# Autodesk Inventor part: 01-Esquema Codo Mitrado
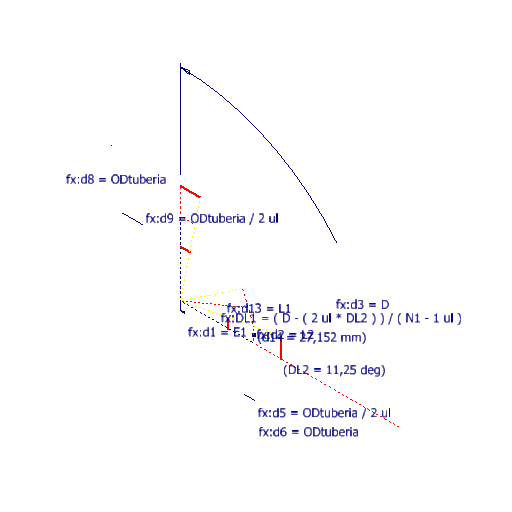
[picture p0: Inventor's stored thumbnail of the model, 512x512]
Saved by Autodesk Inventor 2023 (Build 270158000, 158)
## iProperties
Created: 2023-01
Part Number: 01-Esquema Codo Mitrado
Material: Generic
Document SubType Name: Modeling
Designer: Nelson C Agudelo A
Density: 1 g/cm^3
Appearance: Default
d1: 381,000 mm
d2: 75,786 mm
d3: 90,00 deg
d4: 273,000 mm
d5: 136,500 mm
d6: 273,000 mm
d8: 273,000 mm
d9: 136,500 mm
DL1: 22,50 deg
d13: 151,571 mm
L2: 75,786 mm
L1: 151,571 mm
Recorte: 27,152 mm
D: 90,00 deg
N1: 4,000 ul
E1: 381,000 mm
ODtuberia: 273,000 mm
DL2: 11,25 deg
d14: 27,152 mm
Author: Nelson C Agudelo A
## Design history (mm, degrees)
sketch "Sketch1"
  geometry: L1 (0, 0)-(381, 0); L2 (381, 0)-(381, 75.786); L3 (244.5, 0)-(244.5, 48.634); L4 (517.5, 0)-(517.5, 102.937); L5 (0, 0)-(517.5, 102.937); L6 (0, 0)-(0, 381); L7 (0, 244.5)-(48.634, 244.5); L8 (0, 517.5)-(102.937, 517.5); L9 (0, 381)-(0, 517.5); L10 (0, 0)-(102.937, 517.5); L11 (0, 381)-(75.786, 381); L12 (0, 0)-(322.996, 215.819); L13 (381, 75.786)-(322.996, 215.819); L14 (0, 0)-(351.998, 145.802); L15 (517.5, 0)-(898.5, 0); L16 (381, 0)-(762, 0); L17 (762, 0)-(1143, 0); 1 further point
  constraints: 34 end point, 7 point on line, 5 equal length, 4 perpendicular, 3 horizontal, 2 midpoint, 2 vertical, 1 collinear, 1 horizontal alignment
  dimensions: "d1" = 381 distance of L1.start L1.end (derived); "d2" = 75.78561 distance of L1.end L2.end (derived); "d3" = 90 deg angle of L1 L6 (derived); "d5" = 136.5 horizontal distance of point (381, 37.893) L4.start (derived); "d6" = 273 distance of L3.start L4.start (derived); "DL2" = 11.25 deg angle of L5 L1 (derived); "d8" = 273 distance between parallel lines of L8 L7 (derived); "d9" = 136.5 distance of L6.end L8.start (derived); "DL1" = 22.5 deg angle of L12 L5 (derived); "d13" = 151.57122 distance of L2.end L12.end (derived); "d14" = 27.15154 vertical distance of L4.end L2.end (derived)
other parameters: "d4" = 273 (derived)
